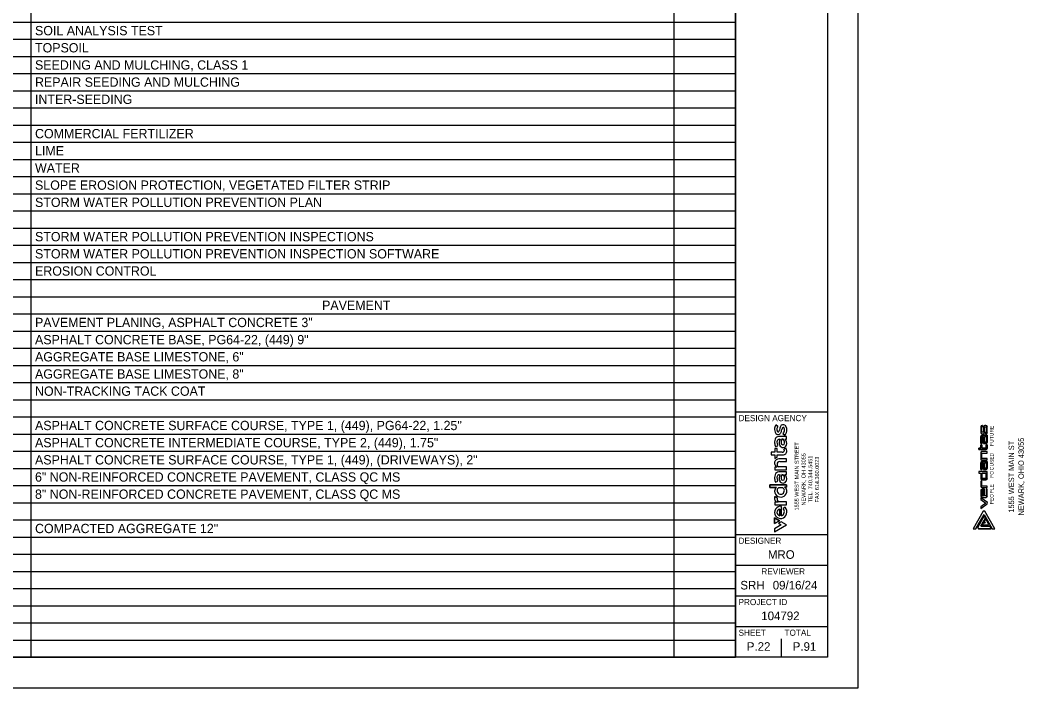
# Model space of a CAD drawing. Extents: x 0 to 36.7, y 0 to 22.
# Drawn here: x 20.33 to 36.72, y 0 to 10.89 of the extents above; entities that cross this region are included whole.
import ezdxf

# ---------------------------------------------------------------- set-up
doc = ezdxf.new("R2010")
doc.units = 0
for name, color, linetype in [('CS-ANNO-TTLB-LOGO', 7, 'Continuous'), ('Default', 7, 'Continuous'), ('SH_Border', 7, 'Continuous'), ('SH_Cut_Line', 7, 'Continuous'), ('SH_Data', 7, 'Continuous'), ('SH_Text', 7, 'Continuous')]:
    doc.layers.add(name, color=color, linetype=linetype)

msp = doc.modelspace()

# ---------------------------------------------------------------- linework, layer by layer
at = {"layer": 'CS-ANNO-TTLB-LOGO'}
for p, q in [((36.033, 4.28), (36.025, 4.28)), ((36.087, 4.28), (36.07, 4.28)), ((36.002, 4.258), (36.002, 4.165)), ((36.025, 4.143), (36.042, 4.143)), ((36.109, 4.165), (36.109, 4.258)), ((36.002, 3.985), (36.002, 4.098)), ((36.002, 3.56), (36.002, 3.673)), ((36.025, 3.392), (36.087, 3.392)), ((36.002, 3.22), (36.002, 3.13)), ((36.109, 3.13), (36.109, 3.242)), ((36.025, 3.107), (36.087, 3.107))]:
    msp.add_line(p, q, dxfattribs=at)
for points in [[(36.047, 4.258), (36.047, 4.171), (36.022, 4.171), (36.022, 4.258), (36.033, 4.258), (36.033, 4.28)], [(36.025, 4.12), (36.109, 4.12), (36.109, 4.008)], [(36.064, 4.165), (36.064, 4.258), (36.089, 4.258), (36.089, 4.171), (36.081, 4.171), (36.081, 4.143), (36.087, 4.143)], [(35.968, 3.909), (36.002, 3.909), (36.002, 3.965), (36.022, 3.965), (36.022, 3.909), (36.089, 3.909), (36.089, 3.965), (36.109, 3.965), (36.109, 3.909)], [(36.087, 3.985), (36.047, 3.985), (36.047, 4.098), (36.022, 4.098), (36.022, 3.985), (36.002, 3.985)], [(36.087, 3.887), (35.968, 3.887), (35.968, 3.909)], [(36.002, 3.836), (36.002, 3.718), (36.109, 3.718), (36.109, 3.74), (36.022, 3.74), (36.022, 3.83), (36.109, 3.83)], [(36.109, 3.83), (36.109, 3.858), (36.025, 3.858)], [(36.087, 3.56), (36.047, 3.56), (36.047, 3.673), (36.022, 3.673), (36.022, 3.56), (36.002, 3.56)], [(36.025, 3.695), (36.109, 3.695), (36.109, 3.583)], [(35.968, 3.527), (35.968, 3.504), (36.002, 3.504), (36.002, 3.414)], [(36.109, 3.414), (36.109, 3.527), (35.968, 3.527)], [(36.109, 3.29), (36.022, 3.29), (36.022, 3.369), (36.002, 3.369), (36.002, 3.29)], [(36.025, 3.268), (36.109, 3.268), (36.109, 3.29)], [(36.109, 3.242), (36.089, 3.242), (36.089, 3.13), (36.064, 3.13), (36.064, 3.242), (36.025, 3.242)]]:
    msp.add_lwpolyline(points, dxfattribs=at)
for points in [[(36.064, 4.098), (36.089, 4.098), (36.089, 4.008), (36.064, 4.008)], [(36.064, 3.673), (36.089, 3.673), (36.089, 3.583), (36.064, 3.583)], [(36.022, 3.504), (36.022, 3.414), (36.089, 3.414), (36.089, 3.504)], [(36.047, 3.22), (36.022, 3.22), (36.022, 3.13), (36.047, 3.13)], [(36.087, 3.014), (36.002, 2.955), (36.002, 2.927), (36.109, 3.002), (36.11, 3.025), (36.003, 3.1), (36.002, 3.073)]]:
    msp.add_lwpolyline(points, close=True, dxfattribs=at)
for centre, start, end in [((36.025, 4.258), 90, 180), ((36.07, 4.258), 90, 180), ((36.087, 4.258), 360, 90), ((36.025, 4.165), 180, 270), ((36.025, 4.098), 90, 180), ((36.042, 4.165), 270, 0), ((36.087, 4.165), 270, 0), ((36.087, 4.008), 270, 360), ((36.025, 3.836), 90, 180), ((36.087, 3.909), 270, 360), ((36.025, 3.673), 90, 180), ((36.087, 3.583), 270, 360), ((36.025, 3.414), 180, 270), ((36.025, 3.29), 180, 270), ((36.087, 3.414), 270, 0), ((36.025, 3.22), 90, 180), ((36.025, 3.13), 180, 270), ((36.087, 3.13), 270, 0)]:
    msp.add_arc(centre, 0.0225, start, end, dxfattribs=at)
at = {"layer": 'Default'}
for p, q in [((20.505, 21.5), (20.505, 0.5)), ((30.995, 21.5), (30.995, 0.5)), ((32, 21.5), (32, 0.5)), ((1.5, 10.86), (32, 10.86)), ((1.5, 10.58), (32, 10.58)), ((1.5, 10.3), (32, 10.3)), ((1.5, 10.02), (32, 10.02)), ((1.5, 9.74), (32, 9.74)), ((1.5, 9.46), (32, 9.46)), ((1.5, 9.18), (32, 9.18)), ((1.5, 8.9), (32, 8.9)), ((1.5, 8.62), (32, 8.62)), ((1.5, 8.34), (32, 8.34)), ((1.5, 8.06), (32, 8.06)), ((1.5, 7.78), (32, 7.78)), ((1.5, 7.5), (32, 7.5)), ((1.5, 7.22), (32, 7.22)), ((1.5, 6.94), (32, 6.94)), ((1.5, 6.66), (32, 6.66)), ((1.5, 6.38), (32, 6.38)), ((1.5, 6.1), (32, 6.1)), ((1.5, 5.82), (32, 5.82)), ((1.5, 5.54), (32, 5.54)), ((1.5, 5.26), (32, 5.26)), ((1.5, 4.98), (32, 4.98)), ((1.5, 4.7), (32, 4.7)), ((1.5, 4.42), (32, 4.42)), ((36.087, 4.28), (36.07, 4.28)), ((1.5, 4.14), (32, 4.14)), ((36.002, 4.258), (36.002, 4.165)), ((36.025, 4.143), (36.042, 4.143)), ((36.109, 4.165), (36.109, 4.258)), ((1.5, 3.86), (32, 3.86)), ((1.5, 3.58), (32, 3.58)), ((1.5, 3.3), (32, 3.3)), ((36.025, 3.392), (36.087, 3.392)), ((36.002, 3.22), (36.002, 3.13)), ((1.5, 3.02), (32, 3.02)), ((36.025, 3.107), (36.087, 3.107)), ((35.952, 2.624), (36.055, 2.807)), ((36.055, 2.807), (36.078, 2.767)), ((1.5, 2.74), (32, 2.74)), ((35.967, 2.596), (35.952, 2.624)), ((36.078, 2.767), (36.004, 2.635)), ((36.004, 2.635), (36.152, 2.635)), ((36.152, 2.635), (36.174, 2.596)), ((1.5, 2.46), (32, 2.46)), ((36.174, 2.596), (35.967, 2.596)), ((1.5, 2.18), (32, 2.18)), ((1.5, 1.9), (32, 1.9)), ((1.5, 1.62), (32, 1.62)), ((1.5, 1.34), (32, 1.34)), ((1.5, 1.06), (32, 1.06)), ((1.5, 0.78), (32, 0.78)), ((1.5, 0.5), (32, 0.5))]:
    msp.add_line(p, q, dxfattribs=at)
for points in [[(36.047, 4.258), (36.047, 4.171), (36.022, 4.171), (36.022, 4.258), (36.033, 4.258), (36.033, 4.28), (36.025, 4.28)], [(36.109, 4.008), (36.109, 4.12), (36.025, 4.12)], [(36.064, 4.165), (36.064, 4.258), (36.089, 4.258), (36.089, 4.171), (36.081, 4.171), (36.081, 4.143), (36.087, 4.143)], [(36.109, 3.909), (36.109, 3.965), (36.089, 3.965), (36.089, 3.909), (36.022, 3.909), (36.022, 3.965), (36.002, 3.965), (36.002, 3.909), (35.968, 3.909), (35.968, 3.887), (36.087, 3.887)], [(36.002, 4.098), (36.002, 3.985), (36.022, 3.985), (36.022, 4.098), (36.047, 4.098), (36.047, 3.985), (36.087, 3.985)], [(36.002, 3.836), (36.002, 3.718), (36.109, 3.718), (36.109, 3.74), (36.022, 3.74), (36.022, 3.83), (36.109, 3.83), (36.109, 3.858), (36.025, 3.858)], [(36.002, 3.673), (36.002, 3.56), (36.022, 3.56), (36.022, 3.673), (36.047, 3.673), (36.047, 3.56), (36.087, 3.56)], [(36.109, 3.583), (36.109, 3.695), (36.025, 3.695)], [(36.109, 3.414), (36.109, 3.527), (35.968, 3.527), (35.968, 3.504), (36.002, 3.504), (36.002, 3.414)], [(36.025, 3.268), (36.109, 3.268), (36.109, 3.29), (36.022, 3.29), (36.022, 3.369), (36.002, 3.369), (36.002, 3.29)], [(36.109, 3.13), (36.109, 3.242), (36.089, 3.242), (36.089, 3.13), (36.064, 3.13), (36.064, 3.242), (36.025, 3.242)]]:
    msp.add_lwpolyline(points, dxfattribs=at)
for points in [[(36.089, 4.098), (36.089, 4.008), (36.064, 4.008), (36.064, 4.098)], [(36.089, 3.673), (36.089, 3.583), (36.064, 3.583), (36.064, 3.673)], [(36.022, 3.504), (36.089, 3.504), (36.089, 3.414), (36.022, 3.414)], [(36.047, 3.22), (36.047, 3.13), (36.022, 3.13), (36.022, 3.22)], [(36.002, 2.955), (36.002, 2.927), (36.109, 3.002), (36.11, 3.025), (36.003, 3.1), (36.002, 3.073), (36.087, 3.014)], [(36.055, 2.83), (36.187, 2.596), (36.232, 2.596), (36.071, 2.881), (36.039, 2.881), (35.878, 2.596), (35.923, 2.596)], [(35.923, 2.596), (36.055, 2.83), (36.187, 2.596), (36.232, 2.596), (36.071, 2.881), (36.039, 2.881), (35.878, 2.596)], [(35.952, 2.624), (35.967, 2.596), (36.174, 2.596), (36.152, 2.635), (36.004, 2.635), (36.078, 2.767), (36.055, 2.807)], [(36.048, 2.691), (36.026, 2.652), (36.116, 2.652), (36.129, 2.675), (36.084, 2.755), (36.062, 2.715), (36.075, 2.691)], [(36.048, 2.691), (36.075, 2.691), (36.062, 2.715), (36.084, 2.755), (36.129, 2.675), (36.116, 2.652), (36.026, 2.652)]]:
    msp.add_lwpolyline(points, close=True, dxfattribs=at)
for centre, start, end in [((36.025, 4.258), 90, 180), ((36.07, 4.258), 90, 180), ((36.087, 4.258), 360, 90), ((36.025, 4.165), 180, 270), ((36.025, 4.098), 90, 180), ((36.042, 4.165), 270, 0), ((36.087, 4.165), 270, 0), ((36.087, 4.008), 270, 0), ((36.025, 3.836), 90, 180), ((36.087, 3.909), 270, 0), ((36.025, 3.673), 90, 180), ((36.087, 3.583), 270, 0), ((36.025, 3.414), 180, 270), ((36.025, 3.29), 180, 270), ((36.087, 3.414), 270, 0), ((36.025, 3.22), 90, 180), ((36.025, 3.13), 180, 270), ((36.087, 3.13), 270, 0)]:
    msp.add_arc(centre, 0.0225, start, end, dxfattribs=at)
at = {"layer": 'SH_Border'}
for p, q in [((32, 0.5), (32, 21.5)), ((32, 4.5), (33.5, 4.5)), ((32, 2.5), (33.5, 2.5)), ((32, 2), (33.5, 2)), ((32, 1.5), (33.5, 1.5)), ((32, 1), (33.5, 1))]:
    msp.add_line(p, q, dxfattribs=at)
msp.add_lwpolyline([(1.5, 21.5), (33.5, 21.5), (33.5, 0.5), (1.5, 0.5)], close=True, dxfattribs=at)
at = {"layer": 'SH_Cut_Line'}
msp.add_lwpolyline([(0, 0), (34, 0), (34, 22), (0, 22)], close=True, dxfattribs=at)
at = {"layer": 'SH_Data'}
for p, q in [((32.75, 3.5), (32.75, 3.5)), ((32.375, 0.675), (32.375, 0.675)), ((32.75, 0.5), (32.75, 0.8))]:
    msp.add_line(p, q, dxfattribs=at)
at = {"layer": 'SH_Text'}
for p, q in [((32.69, 4.263), (32.659, 4.286)), ((32.724, 4.237), (32.717, 4.206)), ((32.753, 4.195), (32.758, 4.215)), ((32.776, 4.147), (32.809, 4.123)), ((32.65, 3.947), (32.654, 3.935)), ((32.713, 4.055), (32.729, 4.055)), ((32.755, 4.055), (32.778, 4.055)), ((32.827, 3.911), (32.792, 3.895)), ((32.713, 3.476), (32.729, 3.476)), ((32.755, 3.476), (32.778, 3.476)), ((32.65, 3.368), (32.654, 3.356)), ((32.681, 3.097), (32.644, 3.119)), ((32.708, 3.268), (32.768, 3.268)), ((32.753, 2.808), (32.753, 2.961)), ((32.723, 2.916), (32.723, 2.809)), ((32.812, 2.946), (32.78, 2.924))]:
    msp.add_line(p, q, dxfattribs=at)
for points in [[(32.691, 4.265), (32.66, 4.288), (32.659, 4.286)], [(32.69, 4.263), (32.691, 4.265)], [(32.803, 4.058), (32.833, 4.058), (32.833, 4.1), (32.708, 4.1)], [(32.803, 4.058), (32.833, 4.058), (32.833, 4.1), (32.708, 4.1)], [(32.724, 4.237), (32.717, 4.206)], [(32.753, 4.195), (32.758, 4.215)], [(32.776, 4.147), (32.774, 4.145), (32.805, 4.12), (32.809, 4.123)], [(32.65, 3.947), (32.654, 3.935)], [(32.654, 3.935), (32.69, 3.949), (32.686, 3.959)], [(32.654, 3.935), (32.69, 3.949), (32.686, 3.959)], [(32.713, 4.055), (32.729, 4.055)], [(32.778, 4.055), (32.755, 4.055)], [(32.763, 3.845), (32.682, 3.845), (32.682, 3.906), (32.643, 3.906), (32.643, 3.845), (32.584, 3.845), (32.584, 3.8), (32.643, 3.8), (32.643, 3.74), (32.682, 3.764), (32.682, 3.8), (32.772, 3.8)], [(32.763, 3.845), (32.682, 3.845), (32.682, 3.906), (32.643, 3.906), (32.643, 3.845), (32.584, 3.845), (32.584, 3.8), (32.643, 3.8), (32.643, 3.74), (32.682, 3.764), (32.682, 3.8), (32.772, 3.8)], [(32.827, 3.911), (32.792, 3.895)], [(32.721, 3.691), (32.833, 3.691), (32.833, 3.736), (32.709, 3.736)], [(32.721, 3.691), (32.833, 3.691), (32.833, 3.736), (32.709, 3.736)], [(32.68, 3.602), (32.643, 3.602), (32.643, 3.559), (32.833, 3.559), (32.833, 3.605), (32.706, 3.605)], [(32.68, 3.602), (32.643, 3.602), (32.643, 3.559), (32.833, 3.559), (32.833, 3.605), (32.706, 3.605)], [(32.803, 3.48), (32.833, 3.48), (32.833, 3.522), (32.708, 3.522)], [(32.803, 3.48), (32.833, 3.48), (32.833, 3.522), (32.708, 3.522)], [(32.713, 3.476), (32.729, 3.476)], [(32.778, 3.476), (32.755, 3.476)], [(32.669, 3.268), (32.562, 3.268), (32.562, 3.313), (32.833, 3.313), (32.833, 3.272), (32.8, 3.272)], [(32.8, 3.272), (32.833, 3.272), (32.833, 3.313), (32.562, 3.313), (32.562, 3.268), (32.669, 3.268)], [(32.65, 3.368), (32.654, 3.356)], [(32.654, 3.356), (32.69, 3.371), (32.686, 3.38)], [(32.654, 3.356), (32.69, 3.371), (32.686, 3.38)], [(32.681, 3.097), (32.644, 3.119)], [(32.708, 3.268), (32.768, 3.268)], [(32.683, 3.029), (32.643, 3.029), (32.643, 2.988), (32.833, 2.988), (32.833, 3.032), (32.707, 3.032)], [(32.683, 3.029), (32.643, 3.029), (32.643, 2.988), (32.833, 2.988), (32.833, 3.032), (32.707, 3.032)], [(32.753, 2.808), (32.753, 2.961)], [(32.723, 2.809), (32.723, 2.916)], [(32.812, 2.946), (32.78, 2.924)], [(32.638, 2.771), (32.638, 2.68), (32.716, 2.726), (32.638, 2.771)], [(32.702, 2.684), (32.746, 2.658), (32.638, 2.596), (32.638, 2.546), (32.833, 2.658), (32.745, 2.709), (32.702, 2.684)]]:
    msp.add_lwpolyline(points, dxfattribs=at)
for points in [[(32.716, 2.726), (32.638, 2.68), (32.638, 2.771)], [(32.702, 2.684), (32.746, 2.658), (32.638, 2.596), (32.638, 2.546), (32.833, 2.658), (32.745, 2.709)]]:
    msp.add_lwpolyline(points, close=True, dxfattribs=at)
for centre, radius, start, end in [((32.769, 4.215), 0.131, 147.2233, 179.842), ((32.769, 4.215), 0.131, 147.2233, 179.842), ((32.77, 4.213), 0.0948, 148.1233, 178.1135), ((32.77, 4.213), 0.0948, 148.1233, 178.1135), ((32.851, 4.208), 0.13, 154.0447, 167.2149), ((32.851, 4.208), 0.13, 154.0447, 167.2149), ((32.778, 4.244), 0.0493, 52.7092, 154.2166), ((32.778, 4.244), 0.0493, 52.7092, 154.2166), ((32.763, 4.228), 0.0711, 22.8278, 50.7157), ((32.763, 4.228), 0.0711, 22.8278, 50.7157), ((32.752, 4.214), 0.114, 179.0109, 203.56), ((32.752, 4.214), 0.114, 179.0109, 203.56), ((32.706, 4.036), 0.0639, 88.076, 162.8642), ((32.706, 4.036), 0.0639, 88.076, 162.8642), ((32.709, 4.195), 0.067, 203.3692, 237.807), ((32.709, 4.195), 0.067, 203.3692, 237.807), ((32.697, 4.177), 0.0458, 238.9453, 317.6829), ((32.697, 4.177), 0.0458, 238.9453, 317.6829), ((32.746, 4.215), 0.0702, 179.0539, 195.6921), ((32.746, 4.215), 0.0702, 179.0539, 195.6921), ((32.711, 4.204), 0.0335, 193.8561, 223.7191), ((32.711, 4.204), 0.0335, 193.8561, 223.7191), ((32.697, 4.191), 0.0148, 224.7822, 330.4366), ((32.697, 4.191), 0.0148, 224.7822, 330.4366), ((32.637, 4.221), 0.0819, 332.9002, 349.3831), ((32.637, 4.221), 0.0819, 332.9002, 349.3831), ((32.65, 4.214), 0.105, 320.1259, 349.7023), ((32.65, 4.214), 0.105, 320.1259, 349.7023), ((32.851, 4.2), 0.0949, 158.1863, 170.6328), ((32.851, 4.2), 0.0949, 158.1863, 170.6328), ((32.779, 4.23), 0.0165, 26.9165, 163.602), ((32.779, 4.23), 0.0165, 26.9165, 163.602), ((32.707, 4.21), 0.0932, 317.363, 356.9244), ((32.707, 4.21), 0.0932, 317.363, 356.9244), ((32.735, 4.209), 0.0655, 357.0077, 26.3112), ((32.735, 4.209), 0.0655, 357.0077, 26.3112), ((32.709, 4.206), 0.129, 320.5166, 0.4341), ((32.709, 4.206), 0.129, 320.5166, 0.4341), ((32.719, 4.209), 0.12, 359.0192, 22.9257), ((32.719, 4.209), 0.12, 359.0192, 22.9257), ((32.766, 4.013), 0.128, 160.8128, 180.9317), ((32.766, 4.013), 0.128, 160.8128, 180.9317), ((32.836, 4.014), 0.199, 180.9467, 199.8354), ((32.836, 4.014), 0.199, 180.9467, 199.8354), ((32.741, 4.008), 0.0647, 163.2522, 179.9971), ((32.741, 4.008), 0.0647, 163.2522, 179.9971), ((32.828, 4.013), 0.152, 181.6616, 200.8714), ((32.828, 4.013), 0.152, 181.6616, 200.8714), ((32.715, 4.017), 0.0374, 92.9671, 165.223), ((32.715, 4.017), 0.0374, 92.9671, 165.223), ((32.822, 3.998), 0.108, 148.3497, 202.4708), ((32.822, 3.998), 0.108, 148.3497, 202.4708), ((32.776, 3.978), 0.0592, 201.6764, 339.7268), ((32.776, 3.978), 0.0592, 201.6764, 339.7268), ((32.849, 4.008), 0.105, 153.8372, 188.8746), ((32.849, 4.008), 0.105, 153.8372, 188.8746), ((32.773, 3.993), 0.0281, 182.327, 355.3778), ((32.773, 3.993), 0.0281, 182.327, 355.3778), ((32.739, 4.004), 0.0637, 348.1247, 52.3678), ((32.739, 4.004), 0.0637, 348.1247, 52.3678), ((32.752, 3.989), 0.0857, 338.2774, 53.7949), ((32.752, 3.989), 0.0857, 338.2774, 53.7949), ((32.766, 3.877), 0.0314, 265.0692, 356.3548), ((32.766, 3.877), 0.0314, 265.0692, 356.3548), ((32.774, 3.864), 0.0642, 267.8641, 1.6213), ((32.774, 3.864), 0.0642, 267.8641, 1.6213), ((32.754, 3.873), 0.0432, 1.8638, 29.9651), ((32.754, 3.873), 0.0432, 1.8638, 29.9651), ((32.744, 3.867), 0.0939, 359.5424, 28.2495), ((32.744, 3.867), 0.0939, 359.5424, 28.2495), ((32.708, 3.666), 0.0703, 88.9896, 246.9111), ((32.708, 3.666), 0.0703, 88.9896, 246.9111), ((32.722, 3.65), 0.0434, 137.3049, 182.9688), ((32.722, 3.65), 0.0434, 137.3049, 182.9688), ((32.726, 3.648), 0.0477, 180.3466, 244.9113), ((32.726, 3.648), 0.0477, 180.3466, 244.9113), ((32.719, 3.648), 0.0433, 86.9739, 132.7421), ((32.719, 3.648), 0.0433, 86.9739, 132.7421), ((32.766, 3.434), 0.128, 160.8128, 180.9317), ((32.766, 3.434), 0.128, 160.8128, 180.9317), ((32.706, 3.458), 0.0639, 88.076, 162.8642), ((32.706, 3.458), 0.0639, 88.076, 162.8642), ((32.741, 3.43), 0.0647, 163.2522, 179.9971), ((32.741, 3.43), 0.0647, 163.2522, 179.9971), ((32.715, 3.439), 0.0374, 92.9671, 165.223), ((32.715, 3.439), 0.0374, 92.9671, 165.223), ((32.822, 3.419), 0.108, 148.3497, 202.4708), ((32.822, 3.419), 0.108, 148.3497, 202.4708), ((32.849, 3.43), 0.105, 153.8372, 188.8746), ((32.849, 3.43), 0.105, 153.8372, 188.8746), ((32.739, 3.426), 0.0637, 348.1247, 52.3678), ((32.739, 3.426), 0.0637, 348.1247, 52.3678), ((32.752, 3.411), 0.0857, 338.2774, 53.7949), ((32.752, 3.411), 0.0857, 338.2774, 53.7949), ((32.836, 3.436), 0.199, 180.9467, 199.8354), ((32.836, 3.436), 0.199, 180.9467, 199.8354), ((32.828, 3.434), 0.152, 181.6616, 200.8714), ((32.828, 3.434), 0.152, 181.6616, 200.8714), ((32.776, 3.4), 0.0592, 201.6764, 339.7268), ((32.776, 3.4), 0.0592, 201.6764, 339.7268), ((32.773, 3.415), 0.0281, 182.327, 355.3778), ((32.773, 3.415), 0.0281, 182.327, 355.3778), ((32.699, 3.09), 0.0628, 152.6524, 255.2929), ((32.699, 3.09), 0.0628, 152.6524, 255.2929), ((32.709, 3.209), 0.0714, 124.2843, 181.2723), ((32.709, 3.209), 0.0714, 124.2843, 181.2723), ((32.738, 3.212), 0.1, 182.7719, 2.9779), ((32.738, 3.212), 0.1, 182.7719, 2.9779), ((32.738, 3.218), 0.0595, 176.4529, 5.055), ((32.738, 3.218), 0.0595, 176.4529, 5.055), ((32.737, 3.217), 0.0586, 119.9007, 175.5797), ((32.737, 3.217), 0.0586, 119.9007, 175.5797), ((32.739, 3.217), 0.0588, 6.0666, 60.041), ((32.739, 3.217), 0.0588, 6.0666, 60.041), ((32.771, 3.211), 0.0671, 5.3084, 64.5252), ((32.771, 3.211), 0.0671, 5.3084, 64.5252), ((32.737, 2.863), 0.0996, 81.0446, 280.2577), ((32.737, 2.863), 0.0996, 81.0446, 280.2577), ((32.732, 3.08), 0.0545, 162.1384, 242.0408), ((32.732, 3.08), 0.0545, 162.1384, 242.0408), ((32.731, 2.862), 0.0543, 98.8378, 261.1622), ((32.731, 2.862), 0.0543, 98.8378, 261.1622), ((32.727, 2.875), 0.072, 290.9232, 42.7391), ((32.727, 2.875), 0.072, 290.9232, 42.7391), ((32.724, 2.874), 0.114, 285.6668, 39.3699), ((32.724, 2.874), 0.114, 285.6668, 39.3699)]:
    msp.add_arc(centre, radius, start, end, dxfattribs=at)

# ---------------------------------------------------------------- texts
at = {"layer": 'Default'}
for s, height, p in [('SOIL ANALYSIS TEST', 0.15153, (20.571, 10.644)), ('TOPSOIL', 0.1515, (20.571, 10.364)), ('SEEDING AND MULCHING, CLASS 1', 0.15153, (20.571, 10.084)), ('REPAIR SEEDING AND MULCHING', 0.15153, (20.571, 9.804)), ('INTER-SEEDING', 0.15153, (20.571, 9.524)), ('COMMERCIAL FERTILIZER', 0.15153, (20.571, 8.964)), ('LIME', 0.1515, (20.571, 8.684)), ('WATER', 0.1515, (20.571, 8.404)), ('SLOPE EROSION PROTECTION, VEGETATED FILTER STRIP', 0.15153, (20.571, 8.124)), ('STORM WATER POLLUTION PREVENTION PLAN', 0.15153, (20.571, 7.844)), ('STORM WATER POLLUTION PREVENTION INSPECTIONS', 0.15153, (20.571, 7.284)), ('STORM WATER POLLUTION PREVENTION INSPECTION SOFTWARE', 0.15153, (20.571, 7.004)), ('EROSION CONTROL', 0.15153, (20.571, 6.724)), ('PAVEMENT', 0.1515, (25.255, 6.164)), ('PAVEMENT PLANING, ASPHALT CONCRETE 3"', 0.15153, (20.571, 5.884)), ('ASPHALT CONCRETE BASE, PG64-22, (449) 9"', 0.15153, (20.571, 5.604)), ('AGGREGATE BASE LIMESTONE, 6"', 0.15153, (20.571, 5.324)), ('AGGREGATE BASE LIMESTONE, 8"', 0.15153, (20.571, 5.044)), ('NON-TRACKING TACK COAT', 0.15153, (20.571, 4.764)), ('ASPHALT CONCRETE SURFACE COURSE, TYPE 1, (449), PG64-22, 1.25"', 0.15153, (20.571, 4.204)), ('ASPHALT CONCRETE INTERMEDIATE COURSE, TYPE 2, (449), 1.75"', 0.15153, (20.571, 3.924)), ('ASPHALT CONCRETE SURFACE COURSE, TYPE 1, (449), (DRIVEWAYS), 2"', 0.15153, (20.571, 3.644)), ('6" NON-REINFORCED CONCRETE PAVEMENT, CLASS QC MS', 0.15153, (20.571, 3.364)), ('8" NON-REINFORCED CONCRETE PAVEMENT, CLASS QC MS', 0.15153, (20.571, 3.084)), ('COMPACTED AGGREGATE 12"', 0.15153, (20.571, 2.524))]:
    msp.add_text(s, height=height, dxfattribs=at).set_placement(p)
for s, p in [('E', (36.21, 4.223)), ('R', (36.21, 4.167)), ('U', (36.21, 4.106)), ('T', (36.21, 4.058)), ('U', (36.21, 3.997)), ('F', (36.21, 3.946)), ('D', (36.21, 3.775)), ('S', (36.21, 3.67)), ('E', (36.21, 3.723)), ('U', (36.21, 3.611)), ('C', (36.21, 3.548)), ('O', (36.21, 3.477)), ('F', (36.21, 3.428)), ('E', (36.21, 3.27)), ('O', (36.21, 3.101)), ('L', (36.21, 3.225)), ('P', (36.21, 3.172)), ('E', (36.21, 3.048)), ('P', (36.21, 2.995))]:
    msp.add_text(s, height=0.0563, rotation=90, dxfattribs=at).set_placement(p)
at = {"layer": 'SH_Data'}
for s, height, p in [('DESIGN AGENCY', 0.1, (32.05, 4.35)), ('DESIGNER', 0.1, (32.05, 2.35)), ('MRO', 0.14, (32.529, 2.105)), ('REVIEWER', 0.1, (32.422, 1.85)), ('SRH', 0.14, (32.08, 1.605)), ('09/16/24', 0.14, (32.608, 1.605)), ('PROJECT ID', 0.1, (32.05, 1.35)), ('104792', 0.14, (32.421, 1.105)), ('SHEET', 0.1, (32.05, 0.85)), ('TOTAL', 0.1, (32.8, 0.85)), ('P.22', 0.14, (32.185, 0.605)), ('P.91', 0.14, (32.934, 0.605))]:
    msp.add_text(s, height=height, dxfattribs=at).set_placement(p)
at = {"layer": 'SH_Text'}
for s, height, p in [('1555 WEST MAIN STREET', 0.06497, (33.032, 2.893)), ('1555 WEST MAIN ST', 0.09, (36.546, 2.858)), ('NEWARK, OHIO 43055', 0.09, (36.706, 2.811)), ('NEWARK, OH 43055', 0.06497, (33.143, 2.975)), ('TEL. 740.344.5451', 0.06497, (33.253, 3.025)), ('FAX 614.360.0023', 0.06497, (33.364, 3.024))]:
    msp.add_text(s, height=height, rotation=90, dxfattribs=at).set_placement(p)

doc.saveas('drawing.dxf')
